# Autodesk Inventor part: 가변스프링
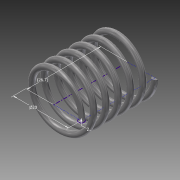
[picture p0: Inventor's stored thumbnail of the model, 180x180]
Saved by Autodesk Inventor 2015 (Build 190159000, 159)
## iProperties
Created: 2020-09
Part Number: 가변스프링
Material: 스테인레스 스틸
Document SubType Name: Modeling
Designer: LINEART-A501-2
Density: 8 g/cm^3
Appearance: 반연마
Mass: 9.31899 g
Surface Area: 23.6157 cm^2
Volume: 1.16487 cm^3
Author: LINEART-A501-2
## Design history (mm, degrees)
sketch "스케치1"
  geometry: L1 (0, 0)-(10, 0); L2 (10, 0)-(10, 26.7); L3 (10, 26.7)-(0, 26.7); L4 (0, 26.7)-(0, 0); C1 r 1 at (10, 0)
  constraints: 8 end point, 2 parallel, 1 centre point, 1 coincident, 1 horizontal, 1 perpendicular
  dimensions: "d1" = 20 diameter of L1.end L4; "d2" = 26.7 distance of L1.start L3.end (derived); "d4" = 2 diameter of C1
feature "코일1" pitch "d5" = 10; turns "d7" = 6; dims "d6" = 26.7 (= d2), "d8" = 0, angle "d9" = 90 deg, angle "d10" = 90 deg, "d11" = 0, "d12" = 0
sketch "스케치2"
  geometry: L1 (-9, 0)-(-11, 0) reference; 1 further point
  constraints: 1 horizontal alignment
extrude "돌출1" cut sketch "스케치2" distance "d13" = 10; taper "d14" = 0 deg
node "작업 평면1"
sketch "스케치3"
  geometry: L1 (0, 0)-(2, 0) reference; 1 further point
  constraints: 1 horizontal alignment
extrude "돌출2" cut sketch "스케치3" distance "d15" = 10; taper "d16" = 0 deg
node "솔리드1"
node "절단 모서리 투영1"
node "절단 모서리 투영2"
